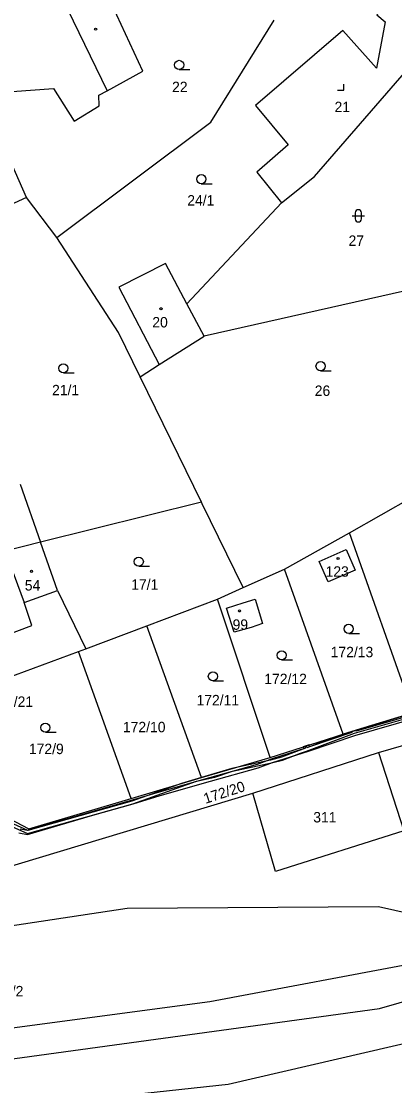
# Model space of a CAD drawing. Extents: x -779723 to -777378, y -1011169 to -1009297.
# Drawn here: x -779101.4 to -779040.4, y -1010475.7 to -1010301.7 of the extents above; entities that cross this region are included whole.
import ezdxf

# ---------------------------------------------------------------- set-up
doc = ezdxf.new("R2010")
doc.units = 0
for name, color, linetype in [('Hranice parcel', 7, 'Continuous'), ('Parcelní čísla', 7, 'Continuous'), ('Poz předměty', 7, 'Continuous'), ('Vnitřní kresba', 7, 'Continuous'), ('Věcná břemena k části', 7, 'Continuous'), ('Značky budov', 7, 'Continuous'), ('Značky kultur', 7, 'Continuous')]:
    doc.layers.add(name, color=color, linetype=linetype)

msp = doc.modelspace()

# ---------------------------------------------------------------- linework, layer by layer
at = {"layer": 'Hranice parcel'}
for p, q in [((-779100.48, -1010330.51), (-779104.32, -1010321.87)), ((-779100.48, -1010330.51), (-779108.53, -1010334.17)), ((-779095.54, -1010337.04), (-779100.48, -1010330.51)), ((-779074.32, -1010347.9), (-779058.85, -1010331.38)), ((-779025.5, -1010342.84), (-779071.49, -1010353.21)), ((-779071.49, -1010353.21), (-779074.32, -1010347.9)), ((-779078.82, -1010357.83), (-779071.49, -1010353.21)), ((-779081.96, -1010359.81), (-779078.82, -1010357.83)), ((-779071.95, -1010380.31), (-779081.96, -1010359.81)), ((-779101.55, -1010377.4), (-779098.22, -1010386.86)), ((-779071.95, -1010380.31), (-779098.22, -1010386.86)), ((-779047.78, -1010385.31), (-779037.39, -1010379.46)), ((-779058.38, -1010391.28), (-779047.78, -1010385.31)), ((-779037.35, -1010414.74), (-779047.78, -1010385.31)), ((-779095.45, -1010394.78), (-779098.22, -1010386.86)), ((-779065.12, -1010394.29), (-779058.38, -1010391.28)), ((-779048.8, -1010418.22), (-779058.38, -1010391.28)), ((-779095.45, -1010394.78), (-779090.81, -1010404.3)), ((-779069.32, -1010396.17), (-779065.12, -1010394.29)), ((-779080.88, -1010400.54), (-779069.32, -1010396.17)), ((-779060.72, -1010422.04), (-779069.32, -1010396.17)), ((-779043.02, -1010421.24), (-778958.54, -1010396.31)), ((-779090.81, -1010404.3), (-779080.88, -1010400.54)), ((-779071.93, -1010425.3), (-779080.88, -1010400.54)), ((-779110.38, -1010411.52), (-779091.99, -1010404.73)), ((-779091.99, -1010404.73), (-779090.81, -1010404.3)), ((-779083.42, -1010428.77), (-779091.99, -1010404.73)), ((-779048.8, -1010418.22), (-779037.35, -1010414.74)), ((-779060.72, -1010422.04), (-779048.8, -1010418.22)), ((-779071.93, -1010425.3), (-779060.72, -1010422.04)), ((-779063.54, -1010427.85), (-779043.02, -1010421.24)), ((-779083.42, -1010428.77), (-779071.93, -1010425.3)), ((-779168.06, -1010459.43), (-779063.54, -1010427.85))]:
    msp.add_line(p, q, dxfattribs=at)
for points in [[(-779107.24, -1010315.22), (-779102.83, -1010313.22), (-779096.1, -1010312.69), (-779092.74, -1010318.04), (-779088.64, -1010315.52), (-779088.67, -1010313.8), (-779087.34, -1010313.07), (-779081.53, -1010309.87), (-779087.9, -1010296.09), (-779090.04, -1010291.48)], [(-779041.67, -1010295.86), (-779043.09, -1010297.32), (-779041.55, -1010298.82), (-779043.27, -1010300.7), (-779041.95, -1010301.84), (-779043.36, -1010309.37), (-779048.83, -1010303.23), (-779063.1, -1010315.51), (-779057.77, -1010321.93), (-779062.91, -1010326.41), (-779058.85, -1010331.38)], [(-779095.54, -1010337.04), (-779070.4, -1010318.23), (-779060.06, -1010301.54)], [(-779058.85, -1010331.38), (-779053.49, -1010327.09), (-779038.46, -1010309.75)], [(-779081.96, -1010359.81), (-779085.48, -1010352.6), (-779095.54, -1010337.04)], [(-779074.32, -1010347.9), (-779077.83, -1010341.29), (-779085.43, -1010345.18), (-779078.82, -1010357.83)], [(-779065.12, -1010394.29), (-779071.81, -1010380.59), (-779071.95, -1010380.31)], [(-779098.22, -1010386.86), (-779103.99, -1010388.3), (-779106.38, -1010388.93)], [(-779046.83, -1010391.44), (-779051.24, -1010393.33), (-779052.71, -1010390), (-779048.3, -1010388.08), (-779046.83, -1010391.44)], [(-779115.59, -1010398.51), (-779110.51, -1010396.79), (-779107.93, -1010403.57), (-779099.61, -1010400.48), (-779100.91, -1010396.73), (-779095.45, -1010394.78)], [(-779066.59, -1010401.56), (-779067.84, -1010397.62), (-779065.12, -1010396.78), (-779063.17, -1010396.18), (-779061.97, -1010400.17), (-779063.82, -1010400.81), (-779066.59, -1010401.56)], [(-779043.02, -1010421.24), (-779038.86, -1010434.01), (-779059.85, -1010440.67), (-779063.54, -1010427.85)], [(-779103.35, -1010431.99), (-779100.12, -1010433.69), (-779083.42, -1010428.77)], [(-779161.4, -1010480.57), (-779135.21, -1010481.09), (-779105.39, -1010479.5), (-779067.56, -1010475.45), (-779027.37, -1010466.13), (-778950.06, -1010444.91)], [(-779030.17, -1010449.35), (-779043.03, -1010446.43), (-779084.08, -1010446.73), (-779168.06, -1010459.43)], [(-779165.75, -1010470.45), (-779127.38, -1010469.51), (-779070.54, -1010461.9), (-779035.24, -1010455.28), (-779030.17, -1010449.35)]]:
    msp.add_lwpolyline(points, dxfattribs=at)
at = {"layer": 'Poz předměty'}
for p, q in [((-779042.85, -1010463.08), (-778940.99, -1010433.26)), ((-779130.44, -1010475.03), (-779042.85, -1010463.08))]:
    msp.add_line(p, q, dxfattribs=at)
at = {"layer": 'Vnitřní kresba'}
for p, q in [((-779097.5, -1010292.06), (-779087.34, -1010313.07)), ((-779103.99, -1010388.3), (-779100.91, -1010396.73))]:
    msp.add_line(p, q, dxfattribs=at)
at = {"layer": 'Věcná břemena k části'}
for points in [[(-779104.36, -1010432.67), (-779100.35, -1010434.49), (-779083.15, -1010429.63), (-779072.72, -1010425.94), (-779069.77, -1010425.26), (-779066.87, -1010424.27), (-779060.52, -1010422.94), (-779058.7, -1010422.47), (-779055.77, -1010421.36), (-779054.79, -1010421), (-779046.94, -1010418.07), (-779025.61, -1010411.99)], [(-779037.35, -1010414.74), (-779046.65, -1010417.57), (-779047.35, -1010417.78), (-779048.8, -1010418.22), (-779054.73, -1010420.45), (-779054.83, -1010420.15), (-779055.31, -1010420.31), (-779055.2, -1010420.62), (-779055.95, -1010420.9), (-779058.86, -1010421.99), (-779060.64, -1010422.46), (-779066.99, -1010423.86), (-779071.93, -1010425.3), (-779075.18, -1010426.28), (-779083.31, -1010429.16), (-779100.31, -1010433.95), (-779104.28, -1010432.17)], [(-779101.74, -1010434.34), (-779100.36, -1010434.61), (-779089.65, -1010431.48), (-779083.07, -1010429.61), (-779078.66, -1010428.28), (-779070.45, -1010425.93), (-779062.67, -1010423.76), (-779060.33, -1010422.87), (-779054.46, -1010421.01), (-779046.91, -1010418.45), (-779036.85, -1010415.56)], [(-779037.03, -1010414.98), (-779046.65, -1010417.75), (-779046.65, -1010417.57), (-779047.35, -1010417.78), (-779047.35, -1010417.96), (-779054.28, -1010420.31), (-779054.34, -1010419.99), (-779055.01, -1010420.21), (-779054.94, -1010420.53), (-779060.53, -1010422.31), (-779062.85, -1010423.18), (-779070.61, -1010425.35), (-779078.82, -1010427.7), (-779083.23, -1010429.03), (-779089.81, -1010430.9), (-779100.38, -1010433.99), (-779101.52, -1010433.78)]]:
    msp.add_lwpolyline(points, dxfattribs=at)
at = {"layer": 'Značky budov'}
for centre in [(-779089.21, -1010303.01), (-779078.55, -1010348.71), (-779049.62, -1010389.53), (-779099.69, -1010391.62), (-779065.73, -1010398.09)]:
    msp.add_circle(centre, 0.175, dxfattribs=at)
at = {"layer": 'Značky kultur'}
for p, q in [((-779075.58, -1010309.61), (-779073.83, -1010309.61)), ((-779049.69, -1010313), (-779048.69, -1010313)), ((-779048.69, -1010313), (-779048.69, -1010312)), ((-779071.96, -1010328.28), (-779070.21, -1010328.28)), ((-779047.31, -1010333.53), (-779045.31, -1010333.53)), ((-779046.81, -1010333.03), (-779046.81, -1010334.03)), ((-779045.81, -1010334.03), (-779045.81, -1010333.03)), ((-779094.48, -1010359.19), (-779092.73, -1010359.19)), ((-779052.48, -1010358.84), (-779050.73, -1010358.84)), ((-779082.17, -1010390.79), (-779080.42, -1010390.79)), ((-779047.88, -1010401.77), (-779046.13, -1010401.77)), ((-779058.84, -1010406.09), (-779057.09, -1010406.09)), ((-779070.06, -1010409.54), (-779068.31, -1010409.54)), ((-779097.42, -1010417.92), (-779095.67, -1010417.92))]:
    msp.add_line(p, q, dxfattribs=at)
for centre in [(-779075.58, -1010308.86), (-779071.96, -1010327.53), (-779094.48, -1010358.44), (-779052.48, -1010358.09), (-779082.17, -1010390.04), (-779047.88, -1010401.02), (-779058.84, -1010405.34), (-779070.06, -1010408.79), (-779097.42, -1010417.17)]:
    msp.add_circle(centre, 0.75, dxfattribs=at)
for centre, start, end in [((-779046.31, -1010333.03), 0, 180), ((-779046.31, -1010334.03), 180, 359.9879)]:
    msp.add_arc(centre, 0.5, start, end, dxfattribs=at)

# ---------------------------------------------------------------- texts
at = {"layer": 'Parcelní čísla'}
for s, p in [('22', (-779076.73, -1010313.31)), ('21', (-779050.2, -1010316.58)), ('24/1', (-779074.25, -1010331.84)), ('27', (-779047.91, -1010338.43)), ('20', (-779079.96, -1010351.76)), ('21/1', (-779096.33, -1010362.85)), ('26', (-779053.43, -1010362.95)), ('123', (-779051.66, -1010392.5)), ('54', (-779100.78, -1010394.76)), ('17/1', (-779083.41, -1010394.63)), ('99', (-779066.85, -1010401.18)), ('172/13', (-779050.83, -1010405.66)), ('172/12', (-779061.67, -1010410.06)), ('172/21', (-779106.38, -1010413.77)), ('172/11', (-779072.74, -1010413.52)), ('172/10', (-779084.76, -1010417.92)), ('172/9', (-779100.11, -1010421.49)), ('311', (-779053.67, -1010432.66)), ('172/2', (-779106.7, -1010461.08))]:
    msp.add_text(s, height=1.7, dxfattribs=at).set_placement(p)
msp.add_text('172/20', height=1.7, rotation=18, dxfattribs=at).set_placement((-779071.27, -1010429.63))

doc.saveas('drawing.dxf')
